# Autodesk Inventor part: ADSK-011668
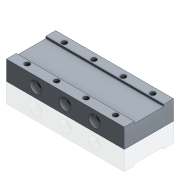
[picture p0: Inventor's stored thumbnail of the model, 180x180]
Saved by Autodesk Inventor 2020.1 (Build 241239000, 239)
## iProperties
Created: 2000-02
Part Number: ADSK-011668
Material: Pearson Aluminium
Document SubType Name: Modeling
Description: PLT-XX,FA,XX,10,060,025,MOUNT,CLAMP
Designer: glanglot
Density: 2.71 g/cm^3
Appearance: Pearson-Aluminum
Mass: 546.163 g
Surface Area: 405.14 cm^2
Volume: 201.536 cm^3
Control State: 0
Checked Out: False
Master: False
Shininess: 35.0
Length Units: 11269
Angle Units: 11279
Time Units: 11290
Mass Units: 11283
Length Display Precision: 3
Angle Display Precision: 2
Compacted: True
Cutlength: 6.0
Material Desc: FLAT,ALUM,1.00X02.500
Material_Number: A090046
Dimensions: 152x25x63,5 mm
Mass: 0,546 kg
DocNumber: ADSK-011668.ipt
Folder: 01 - Themengebiete\Simplification\01 - Packaging machine\
VDS_Category: 3D Komponenten
Density: 2.71
Volumn: 218.1920879090602
Area: 404.55679918904843
PropertySet Name: Model Information
Author: glanglot
Revision Number: -
Title: plate
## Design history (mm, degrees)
node "Solide1"
  node "Extrusion2" dims "d4" = 63.5, "d5" = 0
  node "Hole1" dims "d10" = 6.6, "d11" = 11, "d12" = 6.8, "d13" = 60 deg, "d14" = 19.05, "d15" = 118 deg, "d31" = 6
  node "Hole2" dims "d21" = 9, "d22" = 15, "d23" = 9, "d24" = 60 deg, "d25" = 19.05, "d26" = 118 deg, "d34" = 6
sketch "Sketch1"
  geometry: L1 (-76, -12.5)-(76, -12.5); L2 (76, -12.5)-(76, 12.5); L3 (76, 12.5)-(-76, 12.5); L4 (-76, 12.5)-(-76, -12.5); 3 further points
  constraints: 8 end point, 2 midpoint, 2 parallel, 1 horizontal, 1 horizontal alignment, 1 perpendicular, 1 vertical alignment
  dimensions: "d0" = 152 distance between parallel lines of L4 L2; "d1" = 25 distance between parallel lines of L3 L1
sketch "Sketch2"
  geometry: L1 (152, 63.5)-(0, 63.5) reference; L2 (0, 0)-(0, 63.5) reference; L3 (19, 55.75)-(133, 55.75); L4 (133, 55.75)-(133, 7.75); L5 (133, 7.75)-(19, 7.75); L6 (19, 7.75)-(19, 55.75); 9 further points
  constraints: 8 end point, 4 midpoint, 4 point on line, 3 vertical alignment, 2 parallel, 1 horizontal, 1 horizontal alignment, 1 perpendicular
  dimensions: "d27" = 48 distance of L5.end L3.start; "d28" = 38 distance from line of L6 point (57, 55.75); "d29" = 38 distance of point (57, 55.75) point (95, 55.75) (= d28); "d30" = 38 distance from line of L4 point (95, 55.75) (= d28)
sketch "Skizze4"
  geometry: L1 (152, 0)-(152, -63.5) reference; L2 (0, 0)-(0, -63.5) reference; L3 (152, -12.75)-(0, -12.75); L4 (152, -50.75)-(0, -50.75); 2 further points
  constraints: 8 end point, 4 point on line, 2 vertical, 1 horizontal, 1 midpoint, 1 perpendicular, 4 other
  dimensions: "d35" = 38 distance between parallel lines of L4 L3; "d36" = 19 distance from line of point (152, -31.75) L4 (= 0.5 x d35)
extrude "Extrusion3" cut sketch "Skizze4" distance "d37" = 2.5; taper "d38" = 0 deg
workplane "Arbeitsebene1"
sketch "Sketch3"
  geometry: L1 (-76, -12.5)-(-76, 12.5) reference; L2 (76, -12.5)-(-76, -12.5) reference; L3 (76, 12.5)-(76, -12.5) reference; L4 (-76, 12.5)-(76, 12.5) reference; L5 (-76, 0)-(76, 0); L6 (0, 12.5)-(0, -12.5); 3 further points
  constraints: 5 midpoint, 4 end point, 2 point on line
  dimensions: "d32" = 76 distance of point (38, 0) point (-38, 0); "d33" = 38 distance from line of point (38, 0) L6 (= 0.5 x d32)
node "Corps solides"
node "Corps surfaciques"
